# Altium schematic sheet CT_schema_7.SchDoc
size 277 x 170 mm
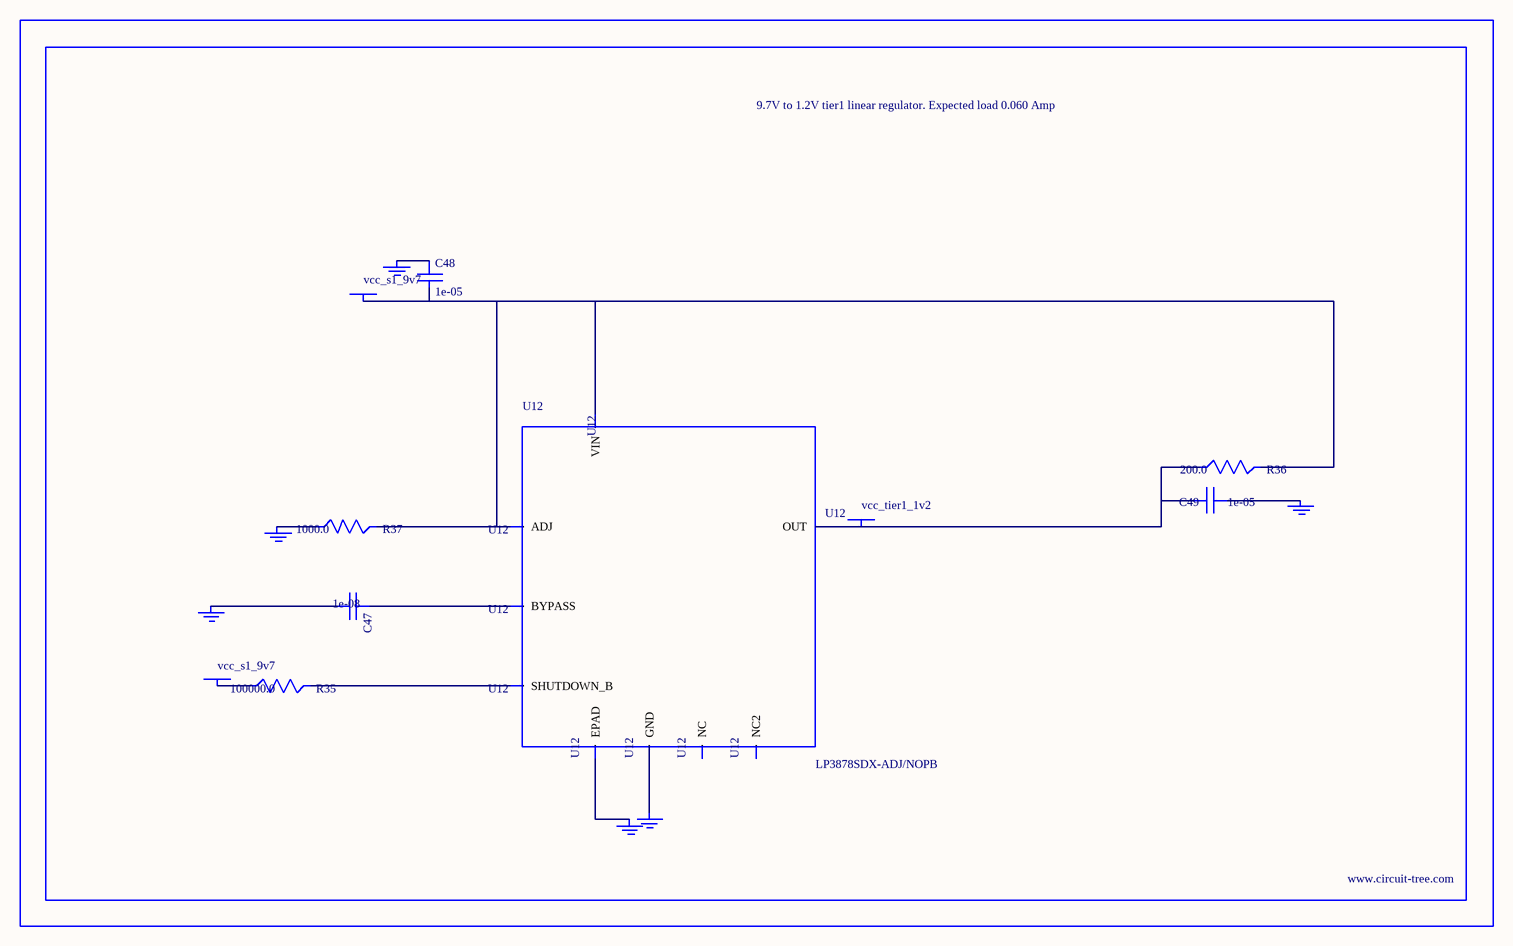
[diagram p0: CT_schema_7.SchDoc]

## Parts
BORDER6  (no value)
C47  1e-08  [C0402]
C48  1e-05  [C1206]
C49  1e-05  [C0805]
GND_INSTANCE_6_0  (no value)
GND_INSTANCE_6_1  (no value)
GND_INSTANCE_6_2  (no value)
GND_INSTANCE_6_3  (no value)
GND_INSTANCE_6_4  (no value)
GND_INSTANCE_6_5  (no value)
POWER_INSTANCE_6_0  vcc_s1_9v7
POWER_INSTANCE_6_1  vcc_s1_9v7
POWER_INSTANCE_6_2  vcc_tier1_1v2
R35  100000.0  [R0603]
R36  200.0  [R0603]
R37  1000.0  [R0603]
U12  LP3878SDX-ADJ/NOPB  [WSON-8]

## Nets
NetC47_1: C47.1 U12.1(BYPASS)
NetC47_2: C47.2 GND_INSTANCE_6_0.0(GND)
NetC48_1: C48.1 GND_INSTANCE_6_1.0(GND)
NetC48_2: C48.2 POWER_INSTANCE_6_0.0(PWR) R36.2 R37.2 U12.4(VIN) U12.6(ADJ)
NetC49_1: C49.1 GND_INSTANCE_6_2.0(GND)
NetC49_2: C49.2 POWER_INSTANCE_6_2.0(PWR) R36.1 U12.5(OUT)
NetGND_INSTANCE_6_3_0: GND_INSTANCE_6_3.0(GND) R37.1
NetGND_INSTANCE_6_4_0: GND_INSTANCE_6_4.0(GND) U12.PAD(EPAD)
NetGND_INSTANCE_6_5_0: GND_INSTANCE_6_5.0(GND) U12.3(GND)
NetPOWER_INSTANCE_6_1_0: POWER_INSTANCE_6_1.0(PWR) R35.1
NetR35_2: R35.2 U12.8(SHUTDOWN_B)

Not connected (* = marked no-connect by the designer): U12 2(NC) 7(NC2)

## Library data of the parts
BORDER6 = BORDER_PAGE6
C47 = C0402C103K3RAC
C48 = C1206C106K3RACTU
C49 = GRM219R60J106ME19D
GND_INSTANCE_6_0-GND_INSTANCE_6_5 = GND
POWER_INSTANCE_6_0-POWER_INSTANCE_6_2 = PWR
R35 = RC0603JR-07100KL
R36 = RC0603JR-07200RL
R37 = RC0603JR-071KL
